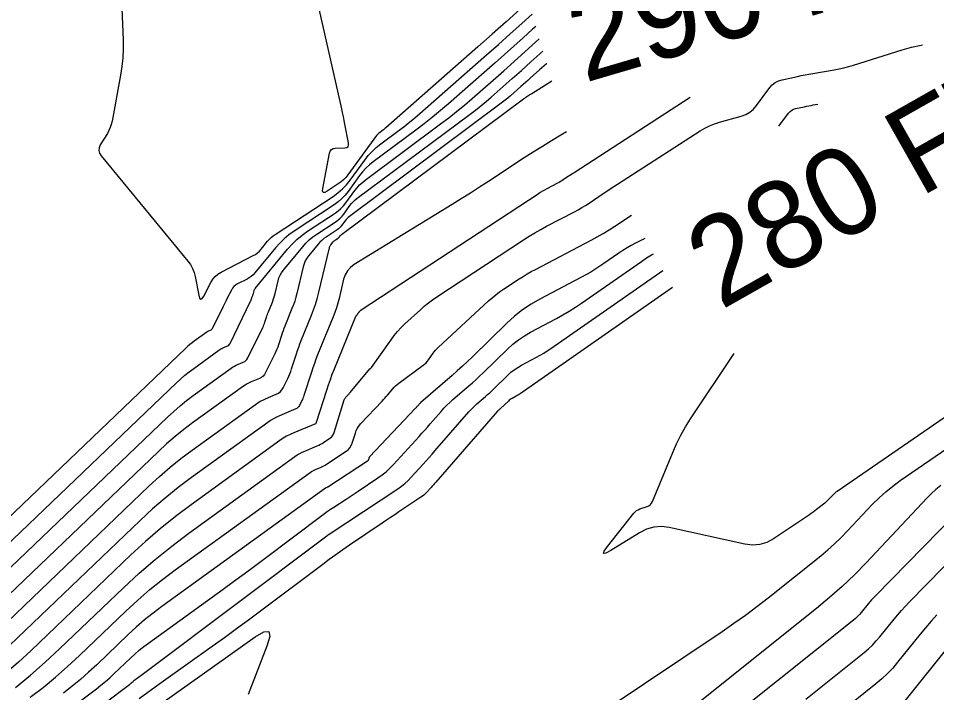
# Model space of a CAD drawing. Extents: x 1768942 to 1774819, y 723037 to 732099.
# Drawn here: x 1770581.3 to 1770644, y 726560.2 to 726606.2 of the extents above; entities that cross this region are included whole.
import ezdxf

# ---------------------------------------------------------------- set-up
doc = ezdxf.new("R2010")
doc.units = 0
doc.layers.add('R_Contour Annot', color=7, linetype='Continuous')
doc.layers.add('R_Contours', color=7, linetype='Continuous')

msp = doc.modelspace()

# ---------------------------------------------------------------- linework, layer by layer
at = {"layer": 'R_Contours'}
for points in [[(1770588.178, 726610.654), (1770588.412, 726604.751), (1770588.419, 726604.144), (1770588.393, 726603.54), (1770588.334, 726602.938), (1770588.24, 726602.338), (1770587.664, 726599.199), (1770587.613, 726598.977), (1770587.542, 726598.763), (1770587.451, 726598.556), (1770587.341, 726598.357), (1770586.86, 726597.576), (1770586.773, 726597.382), (1770586.753, 726597.194), (1770586.799, 726597.01), (1770586.912, 726596.831), (1770592.848, 726589.648), (1770593.024, 726589.406), (1770593.167, 726589.147), (1770593.275, 726588.873), (1770593.348, 726588.582), (1770593.591, 726587.306), (1770593.649, 726587.11), (1770593.724, 726587.036), (1770593.818, 726587.085), (1770593.93, 726587.257), (1770594.412, 726588.187), (1770594.547, 726588.405), (1770594.71, 726588.596), (1770594.901, 726588.758), (1770595.12, 726588.892), (1770597.309, 726590.018), (1770597.461, 726590.105), (1770597.601, 726590.207), (1770597.729, 726590.322), (1770597.847, 726590.451), (1770598.295, 726590.995), (1770598.411, 726591.126), (1770598.537, 726591.247), (1770598.671, 726591.359), (1770598.813, 726591.461), (1770602.765, 726594.064), (1770603.096, 726594.304), (1770603.402, 726594.57), (1770603.683, 726594.862), (1770603.939, 726595.181), (1770604.935, 726596.54), (1770605.177, 726596.847), (1770605.44, 726597.133), (1770605.724, 726597.398), (1770606.029, 726597.643), (1770607.289, 726598.581), (1770607.601, 726598.818), (1770607.909, 726599.062), (1770608.211, 726599.312), (1770608.508, 726599.568), (1770613.256, 726603.739), (1770614.062, 726604.449), (1770614.866, 726605.161), (1770615.667, 726605.876), (1770616.368, 726606.505)], [(1770615.564, 726606.848), (1770614.603, 726605.99), (1770613.638, 726605.135), (1770612.671, 726604.283), (1770606.368, 726598.745), (1770606.315, 726598.7), (1770606.262, 726598.656), (1770606.208, 726598.613), (1770606.153, 726598.572), (1770605.931, 726598.407), (1770605.878, 726598.364), (1770605.828, 726598.317), (1770605.781, 726598.267), (1770605.739, 726598.213), (1770603.782, 726595.542), (1770603.639, 726595.364), (1770603.482, 726595.2), (1770603.311, 726595.052), (1770603.125, 726594.918), (1770602.356, 726594.411), (1770602.194, 726594.328), (1770602.09, 726594.334), (1770602.045, 726594.428), (1770602.059, 726594.61), (1770602.525, 726597.018), (1770602.572, 726597.159), (1770602.653, 726597.261), (1770602.766, 726597.326), (1770602.912, 726597.352), (1770603.562, 726597.38), (1770603.7, 726597.406), (1770603.79, 726597.471), (1770603.832, 726597.573), (1770603.825, 726597.714), (1770603.579, 726598.993), (1770603.527, 726599.259), (1770603.472, 726599.525), (1770603.416, 726599.79), (1770603.358, 726600.055), (1770601.824, 726606.881)], [(1770616.615, 726605.664), (1770616.408, 726605.477), (1770615.769, 726604.904), (1770615.128, 726604.332), (1770614.486, 726603.762), (1770613.842, 726603.195), (1770610.649, 726600.39), (1770610.107, 726599.923), (1770609.555, 726599.467), (1770608.994, 726599.023), (1770608.424, 726598.59), (1770605.515, 726596.423), (1770605.255, 726596.214), (1770605.013, 726595.988), (1770604.789, 726595.745), (1770604.582, 726595.483), (1770603.791, 726594.403), (1770603.583, 726594.144), (1770603.354, 726593.906), (1770603.105, 726593.69), (1770602.836, 726593.495), (1770600.099, 726591.692), (1770599.752, 726591.444), (1770599.426, 726591.173), (1770599.122, 726590.878), (1770598.839, 726590.559), (1770597.425, 726588.844), (1770597.309, 726588.716), (1770597.181, 726588.602), (1770597.043, 726588.502), (1770596.893, 726588.415), (1770596.243, 726588.08), (1770596.111, 726588), (1770595.997, 726587.903), (1770595.9, 726587.789), (1770595.819, 726587.658), (1770595.53, 726587.101), (1770595.458, 726586.961), (1770595.387, 726586.822), (1770595.317, 726586.681), (1770595.247, 726586.54), (1770594.506, 726585.024), (1770594.487, 726584.993), (1770594.464, 726584.966), (1770594.436, 726584.944), (1770594.403, 726584.927), (1770594.263, 726584.868), (1770594.229, 726584.853), (1770594.195, 726584.835), (1770594.163, 726584.816), (1770594.132, 726584.795), (1770593.28, 726584.179), (1770593.13, 726584.067), (1770592.984, 726583.949), (1770592.842, 726583.827), (1770592.704, 726583.699), (1770570.366, 726562.341)], [(1770572.323, 726562.456), (1770592.08, 726581.347), (1770592.358, 726581.604), (1770592.645, 726581.851), (1770592.94, 726582.089), (1770593.244, 726582.316), (1770594.966, 726583.561), (1770595.029, 726583.604), (1770595.095, 726583.643), (1770595.162, 726583.679), (1770595.232, 726583.71), (1770595.515, 726583.828), (1770595.581, 726583.863), (1770595.638, 726583.907), (1770595.686, 726583.961), (1770595.724, 726584.025), (1770597.136, 726586.915), (1770597.145, 726586.933), (1770597.153, 726586.952), (1770597.16, 726586.972), (1770597.167, 726586.991), (1770597.192, 726587.07), (1770597.199, 726587.09), (1770597.206, 726587.109), (1770597.213, 726587.128), (1770597.22, 726587.148), (1770597.281, 726587.297), (1770597.294, 726587.328), (1770597.305, 726587.36), (1770597.314, 726587.393), (1770597.323, 726587.425), (1770597.368, 726587.618), (1770597.381, 726587.66), (1770597.398, 726587.7), (1770597.419, 726587.737), (1770597.445, 726587.772), (1770599.66, 726590.46), (1770599.966, 726590.805), (1770600.294, 726591.123), (1770600.646, 726591.416), (1770601.021, 726591.683), (1770602.907, 726592.926), (1770603.114, 726593.076), (1770603.306, 726593.242), (1770603.482, 726593.426), (1770603.642, 726593.625), (1770604.252, 726594.457), (1770604.411, 726594.658), (1770604.583, 726594.846), (1770604.77, 726595.02), (1770604.97, 726595.181), (1770610.116, 726599.012), (1770610.668, 726599.432), (1770611.21, 726599.862), (1770611.744, 726600.303), (1770612.269, 726600.755), (1770614.427, 726602.651), (1770614.91, 726603.076), (1770615.391, 726603.503), (1770615.872, 726603.932), (1770616.351, 726604.361), (1770616.863, 726604.823)], [(1770581.067, 726560.526), (1770582.091, 726561.37), (1770583.09, 726562.244), (1770584.064, 726563.148), (1770588.445, 726567.337), (1770589.512, 726568.323), (1770590.61, 726569.27), (1770591.74, 726570.178), (1770592.903, 726571.049), (1770600.161, 726576.295), (1770600.321, 726576.404), (1770600.487, 726576.503), (1770600.658, 726576.592), (1770600.834, 726576.672), (1770601.671, 726577.022), (1770601.788, 726577.074), (1770601.903, 726577.132), (1770602.015, 726577.195), (1770602.124, 726577.263), (1770602.555, 726577.545), (1770602.654, 726577.622), (1770602.735, 726577.713), (1770602.8, 726577.816), (1770602.846, 726577.933), (1770603.536, 726580.166), (1770603.555, 726580.216), (1770603.579, 726580.264), (1770603.608, 726580.308), (1770603.643, 726580.349), (1770603.792, 726580.506), (1770603.829, 726580.546), (1770603.865, 726580.586), (1770603.901, 726580.627), (1770603.936, 726580.668), (1770605.288, 726582.287), (1770605.296, 726582.296), (1770605.304, 726582.304), (1770605.313, 726582.311), (1770605.322, 726582.319), (1770605.36, 726582.346), (1770605.369, 726582.354), (1770605.377, 726582.362), (1770605.385, 726582.37), (1770605.392, 726582.379), (1770606.729, 726584.273), (1770606.943, 726584.561), (1770607.172, 726584.836), (1770607.416, 726585.099), (1770607.673, 726585.35), (1770608.732, 726586.326), (1770609.001, 726586.565), (1770609.28, 726586.791), (1770609.567, 726587.006), (1770609.864, 726587.21), (1770615.788, 726591.098), (1770616.171, 726591.343), (1770616.561, 726591.578), (1770616.955, 726591.804), (1770617.356, 726592.02), (1770619.261, 726593.018), (1770619.517, 726593.156), (1770619.768, 726593.301), (1770620.016, 726593.452), (1770620.26, 726593.609), (1770621.229, 726594.251), (1770621.471, 726594.412), (1770621.714, 726594.571), (1770621.957, 726594.73), (1770622.201, 726594.888), (1770627.848, 726598.538), (1770628.163, 726598.726), (1770628.49, 726598.888), (1770628.828, 726599.025), (1770629.178, 726599.137), (1770630.655, 726599.548), (1770630.967, 726599.662), (1770631.248, 726599.822), (1770631.497, 726600.027), (1770631.716, 726600.278), (1770632.613, 726601.491), (1770632.785, 726601.686), (1770632.982, 726601.842), (1770633.205, 726601.957), (1770633.453, 726602.033), (1770634.499, 726602.258), (1770634.76, 726602.313), (1770635.022, 726602.365), (1770635.285, 726602.414), (1770635.548, 726602.46), (1770637.02, 726602.711), (1770637.351, 726602.773), (1770637.68, 726602.847), (1770638.006, 726602.932), (1770638.33, 726603.028), (1770641.659, 726604.082), (1770642.307, 726604.265), (1770642.964, 726604.402), (1770643.046, 726604.414)], [(1770574.28, 726562.571), (1770591.455, 726578.994), (1770591.875, 726579.381), (1770592.307, 726579.754), (1770592.751, 726580.111), (1770593.208, 726580.454), (1770595.801, 726582.327), (1770595.896, 726582.392), (1770595.995, 726582.451), (1770596.096, 726582.504), (1770596.201, 726582.552), (1770596.627, 726582.73), (1770596.727, 726582.782), (1770596.813, 726582.849), (1770596.884, 726582.93), (1770596.942, 726583.027), (1770597.963, 726585.115), (1770598.002, 726585.2), (1770598.039, 726585.286), (1770598.072, 726585.373), (1770598.102, 726585.462), (1770598.216, 726585.819), (1770598.245, 726585.908), (1770598.276, 726585.996), (1770598.309, 726586.084), (1770598.344, 726586.171), (1770598.62, 726586.848), (1770598.675, 726586.991), (1770598.725, 726587.135), (1770598.769, 726587.281), (1770598.807, 726587.429), (1770599.014, 726588.303), (1770599.071, 726588.493), (1770599.148, 726588.673), (1770599.245, 726588.844), (1770599.362, 726589.003), (1770600.7, 726590.627), (1770600.915, 726590.869), (1770601.145, 726591.092), (1770601.392, 726591.297), (1770601.655, 726591.485), (1770602.978, 726592.357), (1770603.123, 726592.462), (1770603.258, 726592.579), (1770603.381, 726592.707), (1770603.494, 726592.847), (1770603.921, 726593.431), (1770604.033, 726593.572), (1770604.154, 726593.704), (1770604.285, 726593.826), (1770604.425, 726593.938), (1770612.142, 726599.684), (1770612.51, 726599.964), (1770612.871, 726600.25), (1770613.226, 726600.544), (1770613.576, 726600.845), (1770615.012, 726602.107), (1770615.334, 726602.39), (1770615.654, 726602.674), (1770615.974, 726602.959), (1770616.293, 726603.245), (1770617.111, 726603.982)], [(1770617.366, 726603.115), (1770617.36, 726603.11), (1770617.193, 726602.978), (1770617.029, 726602.841), (1770616.869, 726602.7), (1770616.235, 726602.13), (1770616.076, 726601.987), (1770615.917, 726601.845), (1770615.758, 726601.704), (1770615.598, 726601.562), (1770614.883, 726600.934), (1770614.709, 726600.784), (1770614.532, 726600.638), (1770614.352, 726600.496), (1770614.169, 726600.357), (1770603.88, 726592.696), (1770603.8, 726592.631), (1770603.724, 726592.561), (1770603.655, 726592.486), (1770603.591, 726592.405), (1770603.345, 726592.069), (1770603.281, 726591.989), (1770603.21, 726591.915), (1770603.132, 726591.848), (1770603.049, 726591.787), (1770602.289, 726591.287), (1770602.138, 726591.179), (1770601.996, 726591.061), (1770601.864, 726590.933), (1770601.74, 726590.794), (1770601.113, 726590.033), (1770600.981, 726589.852), (1770600.871, 726589.66), (1770600.784, 726589.457), (1770600.72, 726589.242), (1770600.291, 726587.434), (1770600.223, 726587.17), (1770600.145, 726586.91), (1770600.057, 726586.653), (1770599.959, 726586.399), (1770599.467, 726585.194), (1770599.405, 726585.039), (1770599.347, 726584.883), (1770599.291, 726584.726), (1770599.239, 726584.567), (1770599.037, 726583.932), (1770598.983, 726583.774), (1770598.924, 726583.619), (1770598.859, 726583.466), (1770598.789, 726583.315), (1770598.16, 726582.028), (1770598.083, 726581.899), (1770597.987, 726581.79), (1770597.873, 726581.701), (1770597.74, 726581.632), (1770597.17, 726581.394), (1770597.03, 726581.33), (1770596.894, 726581.259), (1770596.763, 726581.18), (1770596.636, 726581.094), (1770593.172, 726578.591), (1770592.562, 726578.134), (1770591.968, 726577.656), (1770591.391, 726577.159), (1770590.831, 726576.641), (1770576.236, 726562.687)], [(1770578.193, 726562.802), (1770590.206, 726574.288), (1770590.907, 726574.936), (1770591.629, 726575.558), (1770592.372, 726576.156), (1770593.136, 726576.728), (1770597.47, 726579.86), (1770597.629, 726579.969), (1770597.794, 726580.067), (1770597.964, 726580.156), (1770598.139, 726580.235), (1770598.884, 726580.547), (1770599.035, 726580.626), (1770599.165, 726580.727), (1770599.274, 726580.851), (1770599.362, 726580.998), (1770599.671, 726581.63), (1770599.745, 726581.789), (1770599.814, 726581.951), (1770599.876, 726582.114), (1770599.932, 726582.281), (1770600.263, 726583.316), (1770600.338, 726583.544), (1770600.417, 726583.77), (1770600.501, 726583.994), (1770600.59, 726584.217), (1770601.298, 726585.95), (1770601.439, 726586.315), (1770601.565, 726586.684), (1770601.677, 726587.059), (1770601.775, 726587.438), (1770602.516, 726590.558), (1770602.533, 726590.614), (1770602.555, 726590.667), (1770602.584, 726590.717), (1770602.618, 726590.763), (1770602.781, 726590.961), (1770602.812, 726590.997), (1770602.847, 726591.03), (1770602.884, 726591.061), (1770602.923, 726591.088), (1770603.12, 726591.218), (1770603.141, 726591.234), (1770603.161, 726591.251), (1770603.18, 726591.271), (1770603.197, 726591.291), (1770603.26, 726591.378), (1770603.277, 726591.399), (1770603.295, 726591.419), (1770603.314, 726591.437), (1770603.335, 726591.454), (1770615.793, 726600.729), (1770615.831, 726600.757), (1770615.87, 726600.785), (1770615.909, 726600.811), (1770615.948, 726600.838), (1770616.152, 726600.971), (1770616.169, 726600.982), (1770616.186, 726600.993), (1770616.203, 726601.003), (1770616.22, 726601.014), (1770616.29, 726601.055), (1770616.307, 726601.065), (1770616.325, 726601.076), (1770616.342, 726601.086), (1770616.359, 726601.097), (1770617.708, 726601.955)], [(1770627.181, 726600.815), (1770619.238, 726595.681), (1770619.145, 726595.62), (1770619.051, 726595.559), (1770618.958, 726595.498), (1770618.865, 726595.436), (1770618.493, 726595.19), (1770618.4, 726595.13), (1770618.305, 726595.072), (1770618.208, 726595.016), (1770618.11, 726594.963), (1770617.379, 726594.58), (1770617.225, 726594.497), (1770617.074, 726594.411), (1770616.925, 726594.32), (1770616.778, 726594.226), (1770604.685, 726586.29), (1770604.667, 726586.278), (1770604.651, 726586.266), (1770604.634, 726586.252), (1770604.619, 726586.239), (1770604.557, 726586.182), (1770604.542, 726586.167), (1770604.528, 726586.152), (1770604.514, 726586.135), (1770604.502, 726586.119), (1770604.444, 726586.037), (1770604.43, 726586.018), (1770604.416, 726585.998), (1770604.402, 726585.979), (1770604.388, 726585.96), (1770604.327, 726585.878), (1770604.312, 726585.858), (1770604.299, 726585.837), (1770604.288, 726585.815), (1770604.278, 726585.792), (1770602.836, 726582.263), (1770602.694, 726581.904), (1770602.559, 726581.543), (1770602.431, 726581.18), (1770602.31, 726580.814), (1770601.611, 726578.625), (1770601.609, 726578.617), (1770601.606, 726578.609), (1770601.602, 726578.6), (1770601.598, 726578.593), (1770601.583, 726578.561), (1770601.579, 726578.554), (1770601.573, 726578.548), (1770601.567, 726578.542), (1770601.559, 726578.539), (1770600.077, 726577.919), (1770599.832, 726577.808), (1770599.593, 726577.683), (1770599.363, 726577.545), (1770599.14, 726577.393), (1770593.065, 726573.003), (1770591.994, 726572.201), (1770590.952, 726571.363), (1770589.94, 726570.49), (1770588.957, 726569.582), (1770582.107, 726563.033), (1770581.266, 726562.252), (1770580.403, 726561.497)], [(1770633.234, 726598.858), (1770633.897, 726599.753), (1770633.995, 726599.865), (1770634.109, 726599.954), (1770634.237, 726600.021), (1770634.379, 726600.064), (1770634.979, 726600.193), (1770635.129, 726600.225), (1770635.28, 726600.254), (1770635.43, 726600.283), (1770635.582, 726600.309), (1770635.891, 726600.362)], [(1770618.731, 726598.48), (1770618.325, 726598.24), (1770617.696, 726597.864), (1770617.072, 726597.48), (1770616.452, 726597.089), (1770615.836, 726596.691), (1770613.384, 726595.084), (1770612.77, 726594.684), (1770612.153, 726594.29), (1770611.532, 726593.899), (1770610.909, 726593.514), (1770604.216, 726589.411), (1770603.956, 726589.217), (1770603.748, 726588.985), (1770603.592, 726588.715), (1770603.488, 726588.407), (1770603.178, 726587.1), (1770603.095, 726586.776), (1770602.998, 726586.455), (1770602.89, 726586.138), (1770602.769, 726585.826), (1770601.713, 726583.24), (1770601.598, 726582.949), (1770601.488, 726582.657), (1770601.384, 726582.362), (1770601.286, 726582.065), (1770600.772, 726580.453), (1770600.742, 726580.366), (1770600.71, 726580.28), (1770600.674, 726580.195), (1770600.635, 726580.111), (1770600.473, 726579.78), (1770600.427, 726579.703), (1770600.369, 726579.637), (1770600.301, 726579.584), (1770600.221, 726579.543), (1770599.108, 726579.077), (1770598.898, 726578.982), (1770598.694, 726578.875), (1770598.496, 726578.757), (1770598.305, 726578.627), (1770593.101, 726574.866), (1770592.183, 726574.178), (1770591.291, 726573.461), (1770590.424, 726572.713), (1770589.582, 726571.935), (1770580.15, 726562.917)], [(1770582.078, 726559.852), (1770582.947, 726560.526), (1770583.795, 726561.225), (1770584.622, 726561.948), (1770585.428, 726562.696), (1770588.609, 726565.738), (1770589.416, 726566.484), (1770590.248, 726567.201), (1770591.103, 726567.889), (1770591.983, 726568.548), (1770601.204, 726575.212), (1770601.29, 726575.27), (1770601.379, 726575.324), (1770601.471, 726575.372), (1770601.565, 726575.414), (1770601.95, 726575.575), (1770602.045, 726575.617), (1770602.138, 726575.664), (1770602.228, 726575.715), (1770602.316, 726575.77), (1770603.661, 726576.652), (1770603.801, 726576.761), (1770603.917, 726576.89), (1770604.008, 726577.037), (1770604.075, 726577.202), (1770604.291, 726577.901), (1770604.354, 726578.071), (1770604.435, 726578.23), (1770604.533, 726578.379), (1770604.65, 726578.517), (1770606.123, 726580.079), (1770606.218, 726580.181), (1770606.311, 726580.284), (1770606.403, 726580.389), (1770606.492, 726580.495), (1770606.849, 726580.921), (1770606.941, 726581.025), (1770607.039, 726581.123), (1770607.142, 726581.214), (1770607.251, 726581.299), (1770608.922, 726582.528), (1770609.026, 726582.611), (1770609.124, 726582.703), (1770609.213, 726582.802), (1770609.295, 726582.908), (1770609.606, 726583.349), (1770609.687, 726583.457), (1770609.772, 726583.561), (1770609.864, 726583.659), (1770609.96, 726583.753), (1770613.4, 726586.925), (1770613.641, 726587.138), (1770613.89, 726587.341), (1770614.147, 726587.534), (1770614.412, 726587.716), (1770615.49, 726588.423), (1770615.762, 726588.597), (1770616.037, 726588.763), (1770616.317, 726588.923), (1770616.6, 726589.076), (1770620.413, 726591.073), (1770620.825, 726591.297), (1770621.232, 726591.53), (1770621.633, 726591.774), (1770622.027, 726592.028), (1770623.163, 726592.781)], [(1770624.065, 726591.188), (1770623.434, 726590.866), (1770623.142, 726590.711), (1770622.856, 726590.546), (1770622.575, 726590.371), (1770622.3, 726590.186), (1770621.214, 726589.428), (1770620.939, 726589.243), (1770620.66, 726589.066), (1770620.375, 726588.898), (1770620.084, 726588.739), (1770616.904, 726587.054), (1770616.295, 726586.703), (1770615.716, 726586.312), (1770615.166, 726585.881), (1770614.645, 726585.409), (1770612.29, 726583.115), (1770611.949, 726582.788), (1770611.603, 726582.466), (1770611.252, 726582.149), (1770610.897, 726581.837), (1770608.759, 726579.985), (1770608.752, 726579.979), (1770608.747, 726579.973), (1770608.73, 726579.954), (1770608.724, 726579.948), (1770608.535, 726579.739), (1770608.502, 726579.703), (1770608.469, 726579.667), (1770608.436, 726579.632), (1770608.403, 726579.597), (1770605.268, 726576.273), (1770605.25, 726576.252), (1770605.235, 726576.229), (1770605.222, 726576.205), (1770605.213, 726576.179), (1770605.18, 726576.072), (1770605.169, 726576.046), (1770605.155, 726576.024), (1770605.138, 726576.004), (1770605.116, 726575.987), (1770602.399, 726574.205), (1770602.387, 726574.198), (1770602.375, 726574.191), (1770602.362, 726574.185), (1770602.349, 726574.179), (1770602.297, 726574.157), (1770602.284, 726574.151), (1770602.272, 726574.145), (1770602.259, 726574.137), (1770602.248, 726574.129), (1770591.064, 726566.046), (1770590.466, 726565.599), (1770589.885, 726565.132), (1770589.321, 726564.645), (1770588.772, 726564.138), (1770586.612, 726562.073), (1770586.065, 726561.565), (1770585.503, 726561.074), (1770584.927, 726560.599), (1770584.337, 726560.142)], [(1770577.555, 726553.632), (1770586.597, 726560.431), (1770586.908, 726560.672), (1770587.212, 726560.922), (1770587.508, 726561.181), (1770587.796, 726561.449), (1770588.936, 726562.539), (1770589.225, 726562.806), (1770589.523, 726563.063), (1770589.829, 726563.309), (1770590.144, 726563.545), (1770595.252, 726567.237), (1770595.973, 726567.76), (1770596.691, 726568.286), (1770597.406, 726568.816), (1770598.12, 726569.349), (1770601.99, 726572.256), (1770602.192, 726572.406), (1770602.396, 726572.552), (1770602.603, 726572.694), (1770602.812, 726572.834), (1770603.652, 726573.385), (1770603.862, 726573.523), (1770604.072, 726573.662), (1770604.282, 726573.8), (1770604.491, 726573.939), (1770605.836, 726574.831), (1770606.122, 726575.034), (1770606.395, 726575.254), (1770606.653, 726575.49), (1770606.898, 726575.743), (1770608.647, 726577.669), (1770608.838, 726577.881), (1770609.028, 726578.093), (1770609.217, 726578.307), (1770609.405, 726578.521), (1770610.155, 726579.381), (1770610.346, 726579.592), (1770610.544, 726579.796), (1770610.749, 726579.993), (1770610.961, 726580.183), (1770612.04, 726581.118), (1770612.29, 726581.338), (1770612.537, 726581.561), (1770612.78, 726581.788), (1770613.02, 726582.018), (1770614.679, 726583.633), (1770615.046, 726583.966), (1770615.433, 726584.269), (1770615.841, 726584.545), (1770616.269, 726584.791), (1770618.039, 726585.729), (1770618.476, 726585.969), (1770618.906, 726586.222), (1770619.327, 726586.488), (1770619.74, 726586.768), (1770623.835, 726589.624), (1770624.18, 726589.857), (1770624.533, 726590.077), (1770624.655, 726590.147)], [(1770578.314, 726552.793), (1770588.856, 726560.72), (1770588.888, 726560.745), (1770588.92, 726560.771), (1770588.951, 726560.798), (1770588.981, 726560.826), (1770589.099, 726560.939), (1770589.129, 726560.967), (1770589.16, 726560.994), (1770589.192, 726561.019), (1770589.225, 726561.044), (1770589.719, 726561.401), (1770589.812, 726561.469), (1770589.905, 726561.537), (1770589.998, 726561.605), (1770590.09, 726561.674), (1770602.34, 726570.876), (1770602.353, 726570.886), (1770602.367, 726570.895), (1770602.38, 726570.904), (1770602.394, 726570.914), (1770602.463, 726570.959), (1770602.49, 726570.977), (1770602.504, 726570.986), (1770607.192, 726574.097), (1770607.439, 726574.271), (1770607.674, 726574.46), (1770607.896, 726574.664), (1770608.106, 726574.881), (1770608.922, 726575.78), (1770609.125, 726576.005), (1770609.327, 726576.231), (1770609.529, 726576.458), (1770609.729, 726576.686), (1770612.053, 726579.35), (1770612.182, 726579.493), (1770612.316, 726579.631), (1770612.455, 726579.765), (1770612.599, 726579.894), (1770613.183, 726580.399), (1770613.328, 726580.526), (1770613.471, 726580.656), (1770613.612, 726580.788), (1770613.751, 726580.921), (1770614.713, 726581.858), (1770614.925, 726582.05), (1770615.15, 726582.226), (1770615.386, 726582.386), (1770615.635, 726582.529), (1770616.661, 726583.073), (1770616.915, 726583.212), (1770617.163, 726583.359), (1770617.408, 726583.513), (1770617.648, 726583.675), (1770625.297, 726589.012)], [(1770625.96, 726587.842), (1770615.555, 726580.582), (1770615.489, 726580.538), (1770615.421, 726580.495), (1770615.353, 726580.455), (1770615.283, 726580.416), (1770615.001, 726580.267), (1770614.932, 726580.227), (1770614.867, 726580.183), (1770614.805, 726580.135), (1770614.747, 726580.082), (1770614.482, 726579.824), (1770614.443, 726579.787), (1770614.405, 726579.751), (1770614.365, 726579.715), (1770614.325, 726579.68), (1770614.165, 726579.541), (1770614.125, 726579.506), (1770614.087, 726579.469), (1770614.05, 726579.431), (1770614.014, 726579.391), (1770609.79, 726574.551), (1770609.71, 726574.459), (1770609.629, 726574.367), (1770609.547, 726574.276), (1770609.465, 726574.186), (1770609.137, 726573.824), (1770609.052, 726573.736), (1770608.963, 726573.654), (1770608.868, 726573.578), (1770608.769, 726573.508), (1770607.264, 726572.509), (1770606.979, 726572.32), (1770606.695, 726572.13), (1770606.411, 726571.939), (1770606.128, 726571.748), (1770603.892, 726570.235), (1770603.427, 726569.916), (1770602.967, 726569.591), (1770602.51, 726569.261), (1770602.057, 726568.925), (1770597.808, 726565.736), (1770596.989, 726565.125), (1770596.166, 726564.519), (1770595.339, 726563.918), (1770594.509, 726563.323), (1770591.179, 726560.951), (1770590.348, 726560.355), (1770589.521, 726559.754)], [(1770650.096, 726582.769), (1770637.207, 726573.91), (1770637.129, 726573.854), (1770637.055, 726573.793), (1770636.984, 726573.728), (1770636.916, 726573.66), (1770636.65, 726573.379), (1770636.583, 726573.309), (1770636.513, 726573.243), (1770636.441, 726573.179), (1770636.367, 726573.117), (1770635.812, 726572.673), (1770635.693, 726572.58), (1770635.573, 726572.49), (1770635.451, 726572.403), (1770635.326, 726572.317), (1770632.867, 726570.671), (1770632.405, 726570.421), (1770631.924, 726570.276), (1770631.423, 726570.236), (1770630.902, 726570.301), (1770625.74, 726571.441), (1770625.204, 726571.509), (1770624.686, 726571.474), (1770624.185, 726571.335), (1770623.703, 726571.093), (1770621.755, 726569.883), (1770621.405, 726569.691), (1770621.248, 726569.672), (1770621.285, 726569.826), (1770621.515, 726570.152), (1770623.316, 726572.419), (1770623.404, 726572.516), (1770623.503, 726572.597), (1770623.613, 726572.663), (1770623.733, 726572.713), (1770624.237, 726572.885), (1770624.354, 726572.938), (1770624.452, 726573.01), (1770624.531, 726573.103), (1770624.591, 726573.216), (1770625.985, 726576.579), (1770626.248, 726577.173), (1770626.539, 726577.753), (1770626.857, 726578.317), (1770627.204, 726578.867), (1770630.175, 726583.335)], [(1770621.354, 726558.99), (1770629.364, 726564.352), (1770630.167, 726564.902), (1770630.958, 726565.468), (1770631.737, 726566.052), (1770632.504, 726566.652), (1770636.091, 726569.521), (1770636.572, 726569.919), (1770637.037, 726570.334), (1770637.488, 726570.764), (1770637.924, 726571.211), (1770639.638, 726573.03), (1770640.077, 726573.473), (1770640.538, 726573.89), (1770641.02, 726574.281), (1770641.525, 726574.648), (1770647.547, 726578.787)], [(1770644.297, 726574.31), (1770643.971, 726574.045), (1770643.659, 726573.763), (1770643.362, 726573.464), (1770639.197, 726569.043), (1770638.393, 726568.219), (1770637.561, 726567.424), (1770636.702, 726566.659), (1770635.815, 726565.924), (1770626.486, 726558.463)], [(1770645.297, 726572.363), (1770639.827, 726566.783), (1770639.697, 726566.648), (1770639.571, 726566.509), (1770639.448, 726566.368), (1770639.329, 726566.224), (1770638.859, 726565.641), (1770638.737, 726565.499), (1770638.609, 726565.364), (1770638.473, 726565.236), (1770638.331, 726565.115), (1770630.547, 726558.896)], [(1770635.08, 726559.73), (1770639.055, 726562.906), (1770639.349, 726563.154), (1770639.628, 726563.417), (1770639.892, 726563.695), (1770640.141, 726563.988), (1770641.11, 726565.188), (1770641.355, 726565.485), (1770641.608, 726565.775), (1770641.867, 726566.06), (1770642.134, 726566.338), (1770645.642, 726569.917)], [(1770644.037, 726565.472), (1770643.644, 726565.041), (1770643.262, 726564.601), (1770642.89, 726564.151), (1770641.351, 726562.243), (1770641.011, 726561.845), (1770640.651, 726561.466), (1770640.271, 726561.108), (1770639.87, 726560.77), (1770638.229, 726559.458)], [(1770590.207, 726558.822), (1770597.442, 726563.974), (1770598.034, 726564.321), (1770598.367, 726564.333), (1770598.438, 726564.008), (1770598.25, 726563.348), (1770596.974, 726560.034)], [(1770644.973, 726563.49), (1770641.831, 726559.596)]]:
    msp.add_lwpolyline(points, dxfattribs=at)

# ---------------------------------------------------------------- texts
at = {"layer": 'R_Contour Annot'}
for s, rotation, p in [('290 FT', 16.41325, (1770619.942, 726601.81)), ('280 FT', 29.52257, (1770629.267, 726586.268))]:
    msp.add_text(s, height=6, rotation=rotation, dxfattribs=at).set_placement(p)

doc.saveas('drawing.dxf')
